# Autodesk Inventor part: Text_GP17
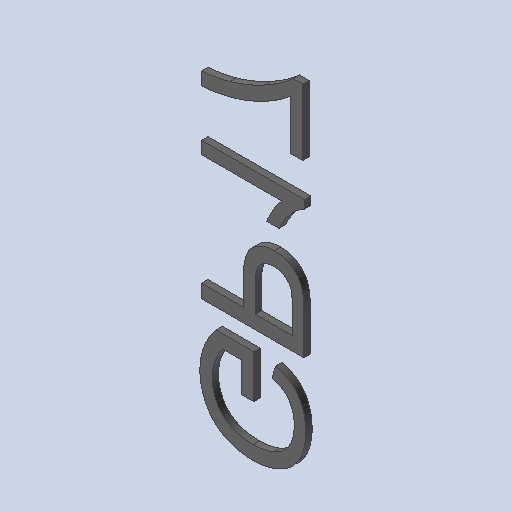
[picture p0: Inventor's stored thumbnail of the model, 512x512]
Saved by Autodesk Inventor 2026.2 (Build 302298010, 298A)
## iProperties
Created: 2026-10
Part Number: Text_GP17
Material: Générique
Document SubType Name: Modeling
Designer: mel
Density: 1 g/cm^3
Appearance: Par défaut
Author: mel
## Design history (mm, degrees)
feature "Base1"
feature "Base2"
feature "Base3"
feature "Base4"
node "Solide1"
node "Solide2"
node "Solide3"
node "Solide4"
